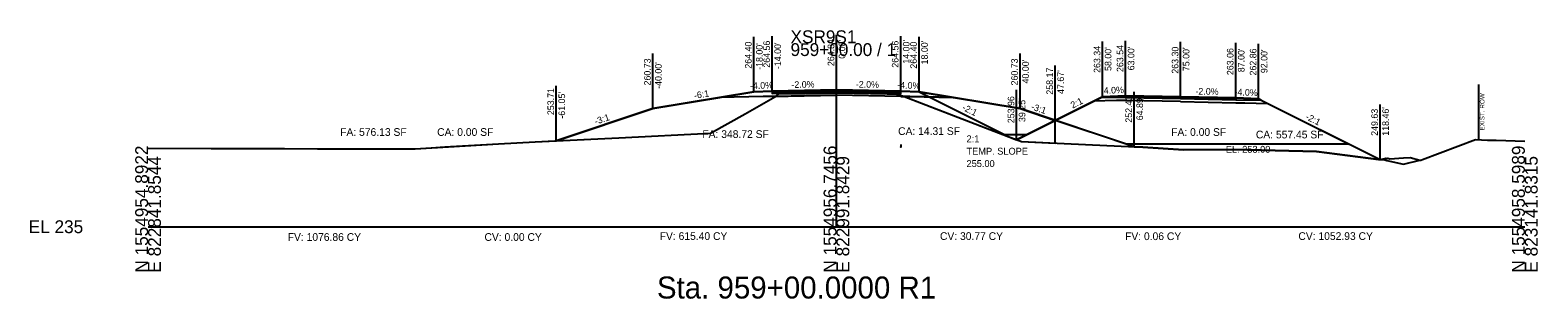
# Model space of a CAD drawing. Extents: x -26 to 823017, y -16 to 1558356.
# Drawn here: x -25.7 to 302.8, y 6984.3 to 7042.8 of the extents above; entities that cross this region are included whole.
import ezdxf

# ---------------------------------------------------------------- set-up
doc = ezdxf.new("R2010")
doc.units = 0
for name, color, linetype in [('ASPHALT_19MM1', 7, 'Continuous'), ('ASPHALT_9_5MM1', 7, 'Continuous'), ('CONST_DCH', 7, 'Continuous'), ('CONST_LV3', 7, 'Continuous'), ('Default', 7, 'Continuous'), ('Draft_XS_Grid', 7, 'Continuous'), ('Draft_XS_Text', 7, 'Continuous'), ('DTM_CORRIDOR', 7, 'Continuous'), ('DTM_P_FINISHED_GRADE2', 7, 'Continuous'), ('DTM_TEMP_DROP', 7, 'Continuous'), ('DTM_X_GROUND', 7, 'Continuous'), ('PROFILES_DCH_2', 7, 'Continuous'), ('SLOPE_STAKES_FILL', 7, 'Continuous'), ('XS_CELL', 7, 'Continuous'), ('XS_M_SHAPES_EARTHWORK', 7, 'Continuous'), ('XS_P_ASPHALT', 7, 'Continuous'), ('XS_P_DR_GRAVEL', 7, 'Continuous'), ('XS_P_GROUND', 7, 'Continuous'), ('XS_P_NULL_POINT', 7, 'Continuous'), ('XS_P_SHOULDER', 7, 'Continuous'), ('XS_P_SUBGRADE_GRANULAR', 7, 'Continuous'), ('XS_P_SUBGRADE_MILLING', 7, 'Continuous'), ('XS_P_SUBGRADE_UNDERCUT', 7, 'Continuous'), ('XS_P_TX_CLEARZONE', 7, 'Continuous'), ('XS_P_TX_FS_BS', 7, 'Continuous'), ('XS_SHEET_EW_TX_AREA', 7, 'Continuous'), ('XS_SHEET_EW_TX_VOLUME', 7, 'Continuous'), ('XS_X_ROW', 7, 'Continuous')]:
    doc.layers.add(name, color=color, linetype=linetype)

msp = doc.modelspace()

# ---------------------------------------------------------------- linework, layer by layer
at = {"layer": 'ASPHALT_19MM1'}
for points in [[(136, 7029.27), (136, 7029.06), (150, 7029.34), (150, 7029.34), (150, 7029.34), (164, 7029.06), (164, 7029.27), (164, 7029.27), (150, 7029.55), (150, 7029.55), (150, 7029.55), (136, 7029.27), (136, 7029.27)], [(213, 7028.16), (225, 7027.92), (237, 7027.68), (237, 7027.89), (225, 7028.13), (213, 7028.37), (213, 7028.16)]]:
    msp.add_lwpolyline(points, dxfattribs=at)
at = {"layer": 'ASPHALT_9_5MM1'}
msp.add_lwpolyline([(136, 7029.56), (136, 7029.43), (150, 7029.71), (150, 7029.71), (150, 7029.71), (164, 7029.43), (164, 7029.56), (164, 7029.56), (150, 7029.84), (150, 7029.84), (150, 7029.84), (136, 7029.56), (136, 7029.56)], dxfattribs=at)
at = {"layer": 'CONST_DCH'}
msp.add_lwpolyline([(213, 7028.37), (225, 7028.13), (237, 7027.89), (237, 7028.06), (225, 7028.3), (213, 7028.54), (213, 7028.37)], dxfattribs=at)
at = {"layer": 'CONST_LV3'}
for points in [[(110, 7025.73), (124.59, 7028.16), (124.59, 7028.16)], [(150, 7029.84), (164, 7029.56)], [(168, 7029.4), (164, 7029.56), (164, 7029.56)], [(190, 7025.73), (175.41, 7028.16), (175.41, 7028.16)], [(189.25, 7018.96), (189.25, 7018.96), (208, 7028.34), (208, 7028.34), (213, 7028.54)], [(197.67, 7023.17), (197.67, 7023.17), (208, 7028.34), (208, 7028.34), (213, 7028.54), (225, 7028.3), (225, 7028.3), (237, 7028.06), (237, 7028.06), (237, 7028.06), (242, 7027.86), (242, 7027.86), (242, 7027.86), (242, 7027.86), (242, 7027.86), (242, 7027.86), (242, 7027.86), (242, 7027.86), (268.46, 7014.63), (269.52, 7014.87), (269.69, 7014.91), (269.7, 7014.91), (269.94, 7014.87), (270.16, 7014.91), (270.59, 7014.79), (273.59, 7015), (275, 7015.11), (277.13, 7014.48), (277.36, 7014.53), (277.7, 7014.68), (289.27, 7019), (291.84, 7018.88), (293.73, 7018.86), (300, 7018.65)], [(242, 7027.86), (268.46, 7014.63)], [(0, 7017.11), (13.73, 7017.07), (29.7, 7017.03), (36.9, 7017.01), (53.92, 7016.98), (58.23, 7017.01), (61.68, 7017.21), (64.64, 7017.39), (65.92, 7017.46), (76.37, 7018.08), (84.38, 7018.48), (88.61, 7018.7), (88.95, 7018.71)], [(164, 7017.9), (164, 7017.36), (164, 7017.38)]]:
    msp.add_lwpolyline(points, dxfattribs=at)
at = {"layer": 'Default'}
msp.add_lwpolyline([(136, 7029.43), (136, 7029.27), (150, 7029.55), (150, 7029.55), (150, 7029.55), (164, 7029.27), (164, 7029.43), (164, 7029.43), (150, 7029.71), (150, 7029.71), (150, 7029.71), (136, 7029.43), (136, 7029.43)], dxfattribs=at)
at = {"layer": 'DTM_P_FINISHED_GRADE2'}
msp.add_lwpolyline([(88.95, 7018.71), (110, 7025.73), (110, 7025.73), (132, 7029.4), (136, 7029.56), (150, 7029.84), (164, 7029.56), (168, 7029.4), (168, 7029.4), (190, 7025.73), (190, 7025.73), (197.67, 7023.17), (197.67, 7023.17)], dxfattribs=at)
at = {"layer": 'DTM_X_GROUND'}
for points in [[(0, 7017.11), (13.73, 7017.07), (29.7, 7017.03), (36.9, 7017.01), (53.92, 7016.98), (58.23, 7017.01), (61.68, 7017.21), (64.64, 7017.39), (65.92, 7017.46), (76.37, 7018.03), (84.38, 7018.47), (88.61, 7018.7), (88.95, 7018.71), (110, 7025.73), (110, 7025.73), (132, 7029.4), (132, 7029.4), (136, 7029.56), (136, 7029.56), (136, 7029.56), (150, 7029.84), (150, 7029.84), (164, 7029.56), (168, 7029.4), (168, 7029.4), (190, 7025.73), (190, 7025.73), (197.67, 7023.17), (197.67, 7023.17), (197.67, 7023.17), (208, 7028.34), (208, 7028.34), (213, 7028.54), (225, 7028.3), (225, 7028.3), (237, 7028.06), (237, 7028.06), (237, 7028.06), (242, 7027.86), (242, 7027.86), (242, 7027.86), (242, 7027.86), (242, 7027.86), (242, 7027.86), (242, 7027.86), (242, 7027.86), (268.46, 7014.63), (269.52, 7014.87), (269.69, 7014.91), (269.7, 7014.91), (269.94, 7014.87), (270.16, 7014.91), (270.59, 7014.79), (273.59, 7015), (275, 7015.11), (277.13, 7014.48), (277.36, 7014.53), (277.7, 7014.68), (289.27, 7019), (291.84, 7018.88), (293.73, 7018.86), (300, 7018.65)], [(0, 7017.11), (13.73, 7017.07), (29.7, 7017.03), (36.9, 7017.01), (53.92, 7016.98), (58.23, 7017.01), (76.37, 7018.08), (84.38, 7018.48), (102.55, 7019.4), (122.59, 7020.4), (130.09, 7024.59), (136.7, 7028.35), (137.06, 7028.67), (137.42, 7028.96), (143.28, 7029.07), (150.17, 7029.21), (161.03, 7028.98), (162.9, 7028.94), (163.17, 7028.86), (164.42, 7028.5), (186.29, 7020.1), (190.33, 7018.55), (208.91, 7017.7), (216.77, 7017.35), (225.63, 7016.77), (236.61, 7016.83), (254.59, 7016.41), (268.12, 7014.64), (269.52, 7014.59), (269.94, 7014.45), (270.59, 7014.32), (273.59, 7013.65), (277.13, 7014.48), (277.36, 7014.53), (277.7, 7014.68), (289.27, 7019), (291.84, 7018.88), (293.73, 7018.86), (300, 7018.65)], [(0, 7017.11), (13.73, 7017.07), (29.7, 7017.03), (36.9, 7017.01), (53.92, 7016.98), (58.23, 7017.01), (76.37, 7018.08), (84.38, 7018.48), (102.55, 7019.4), (122.59, 7020.4), (130.09, 7024.59), (136.7, 7028.35), (137.06, 7028.67), (137.42, 7028.96), (143.28, 7029.07), (150.17, 7029.21), (161.03, 7028.98), (162.9, 7028.94), (163.17, 7028.86), (164.42, 7028.5), (186.29, 7020.1), (189.25, 7018.96), (189.25, 7018.96), (189.25, 7018.96), (208, 7028.34), (208, 7028.34), (213, 7028.54), (225, 7028.3), (225, 7028.3), (237, 7028.06), (237, 7028.06), (237, 7028.06), (242, 7027.86), (242, 7027.86), (242, 7027.86), (242, 7027.86), (242, 7027.86), (242, 7027.86), (242, 7027.86), (242, 7027.86), (268.46, 7014.63), (269.52, 7014.87), (269.69, 7014.91), (269.7, 7014.91), (269.94, 7014.87), (270.16, 7014.91), (270.59, 7014.79), (273.59, 7015), (275, 7015.11), (277.13, 7014.48), (277.36, 7014.53), (277.7, 7014.68), (289.27, 7019), (291.84, 7018.88), (293.73, 7018.86), (300, 7018.65)]]:
    msp.add_lwpolyline(points, dxfattribs=at)
at = {"layer": 'XS_CELL'}
for p, q in [((150, 7000), (150, 7040)), ((0, 7000), (150, 7000)), ((150, 7000), (300, 7000))]:
    msp.add_line(p, q, dxfattribs=at)
at = {"layer": 'XS_M_SHAPES_EARTHWORK'}
for points in [[(88.95, 7018.71), (102.55, 7019.4), (122.59, 7020.4), (130.09, 7024.59), (136.7, 7028.35), (136.76, 7028.41), (136, 7028.39), (134, 7028.35), (124.59, 7028.16), (110, 7025.73)], [(136.76, 7028.41), (137.06, 7028.67), (137.42, 7028.96), (143.28, 7029.07), (150.17, 7029.21), (161.03, 7028.98), (162.9, 7028.94), (163.17, 7028.86), (164.42, 7028.5), (164.74, 7028.38), (164, 7028.39), (150, 7028.67)], [(164.74, 7028.38), (186.29, 7020.1), (190.33, 7018.55), (197.67, 7018.21), (197.67, 7023.17), (190, 7025.73), (175.41, 7028.16), (166, 7028.35)]]:
    msp.add_lwpolyline(points, close=True, dxfattribs=at)
at = {"layer": 'XS_P_DR_GRAVEL'}
for points in [[(208, 7028.34), (208, 7028.34), (207.86, 7028.27), (213, 7028.16), (213, 7028.16), (213, 7028.16), (213, 7028.54), (208, 7028.34)], [(242, 7027.86), (237, 7028.06), (237, 7027.68), (237, 7027.68), (242.57, 7027.57), (242.57, 7027.57), (242.57, 7027.57), (242, 7027.86), (242, 7027.86)]]:
    msp.add_lwpolyline(points, dxfattribs=at)
at = {"layer": 'XS_P_GROUND'}
for p in [(168, 7029.4), (191.32, 7020)]:
    msp.add_line(p, (186.79, 7020), dxfattribs=at)
for points in [[(132, 7029.4), (110, 7025.73), (88.95, 7018.71)], [(197.67, 7023.17), (197.67, 7023.17), (190, 7025.73), (168, 7029.4), (168, 7029.4)], [(214.89, 7017.43), (214.89, 7017.43), (190, 7025.73), (168, 7029.4), (168, 7029.4)], [(208, 7028.34), (189.25, 7018.96)], [(242, 7027.86), (268.46, 7014.63)], [(268.46, 7014.63), (268.12, 7014.64), (268.12, 7014.64), (254.59, 7016.41), (254.59, 7016.41), (254.59, 7016.41), (236.61, 7016.83), (236.61, 7016.83), (225.63, 7016.77), (216.77, 7017.35), (216.77, 7017.35), (214.89, 7017.43), (214.89, 7017.43)], [(214.89, 7017.43), (214.89, 7017.43), (216.77, 7017.35), (216.77, 7017.35), (225.63, 7016.77), (236.61, 7016.83), (236.61, 7016.83), (254.59, 7016.41), (254.59, 7016.41), (254.59, 7016.41), (268.12, 7014.64), (268.12, 7014.64), (268.46, 7014.63)]]:
    msp.add_lwpolyline(points, dxfattribs=at)
at = {"layer": 'XS_P_SHOULDER'}
for points in [[(136, 7029.56), (132, 7029.4)], [(164, 7029.56), (168, 7029.4)], [(208, 7028.34), (208, 7028.34), (213, 7028.54)], [(242, 7027.86), (242, 7027.86), (237, 7028.06)]]:
    msp.add_lwpolyline(points, dxfattribs=at)
at = {"layer": 'XS_P_SUBGRADE_GRANULAR'}
for points in [[(136, 7028.39), (134, 7028.35), (124.59, 7028.16)], [(136, 7028.39), (150, 7028.67), (150, 7028.67)], [(164, 7028.39), (150, 7028.67), (150, 7028.67)], [(164, 7028.39), (166, 7028.35), (175.41, 7028.16)], [(213, 7027.5), (211, 7027.54), (206, 7027.34)], [(225, 7027.26), (213, 7027.5)], [(225, 7027.26), (237, 7027.02)], [(237, 7027.02), (239, 7026.98), (243.96, 7026.88)]]:
    msp.add_lwpolyline(points, dxfattribs=at)
at = {"layer": 'XS_P_SUBGRADE_UNDERCUT'}
msp.add_lwpolyline([(213.19, 7018), (197.67, 7023.17), (208, 7028.34), (213, 7028.54), (225, 7028.3), (237, 7028.06), (242, 7027.86), (261.72, 7018)], close=True, dxfattribs=at)
at = {"layer": 'XS_P_TX_CLEARZONE'}
for p, q in [((132, 7029.4), (132, 7041.4)), ((136, 7029.56), (136, 7041.56)), ((150, 7029.84), (150, 7041.84)), ((164, 7029.56), (164, 7041.56)), ((168, 7029.4), (168, 7041.4)), ((168, 7029.4), (168, 7041.4)), ((213, 7028.54), (213, 7040.54)), ((110, 7025.73), (110, 7037.73)), ((190, 7025.73), (190, 7037.73)), ((190, 7025.73), (190, 7037.73)), ((208, 7028.34), (208, 7040.34)), ((225, 7028.3), (225, 7040.3)), ((237, 7028.06), (237, 7040.06)), ((242, 7027.86), (242, 7039.86)), ((197.67, 7023.17), (197.67, 7035.17)), ((88.95, 7018.71), (88.95, 7030.71)), ((189.25, 7018.96), (189.25, 7029.86)), ((214.89, 7017.43), (214.89, 7029.43)), ((268.46, 7014.63), (268.46, 7026.63))]:
    msp.add_line(p, q, dxfattribs=at)
at = {"layer": 'XS_X_ROW'}
msp.add_line((290, 7018.97), (290, 7030.97), dxfattribs=at)

# ---------------------------------------------------------------- texts
at = {"layer": 'CONST_DCH'}
for p in [(189.17, 7018.84), (268.38, 7014.51), (268.38, 7014.51)]:
    msp.add_text('X', height=0.24, dxfattribs=at).set_placement(p)
at = {"layer": 'Draft_XS_Grid'}
msp.add_text('-', height=0.0001, dxfattribs=at).set_placement((0, 7000))
at = {"layer": 'Draft_XS_Text'}
msp.add_text('Sta. 959+00.0000 R1', height=4.8, dxfattribs=at).set_placement((110.88, 6984.35))
at = {"layer": 'DTM_CORRIDOR'}
for p in [(212.92, 7028.42), (224.92, 7028.18), (236.92, 7027.94)]:
    msp.add_text('X', height=0.24, dxfattribs=at).set_placement(p)
at = {"layer": 'DTM_TEMP_DROP'}
for p in [(135.92, 7029.44), (149.92, 7029.72), (163.92, 7029.44)]:
    msp.add_text('X', height=0.24, dxfattribs=at).set_placement(p)
at = {"layer": 'PROFILES_DCH_2'}
for p in [(167.92, 7029.28), (189.92, 7025.61), (214.81, 7017.31), (268.38, 7014.51)]:
    msp.add_text('X', height=0.24, dxfattribs=at).set_placement(p)
at = {"layer": 'SLOPE_STAKES_FILL'}
for p in [(197.59, 7023.05), (88.87, 7018.59)]:
    msp.add_text('X', height=0.24, dxfattribs=at).set_placement(p)
at = {"layer": 'XS_CELL'}
for s, p in [('XSR9S1', (140, 7040)), ('959+00.00 / 1', (140, 7037.2)), ('EL 235', (-26, 6998.6))]:
    msp.add_text(s, height=2.8, dxfattribs=at).set_placement(p)
for s, p in [('N 1554954.8922', (0, 6990)), ('N 1554956.7456', (150, 6990)), ('N 1554958.5989', (300, 6990)), ('E 822841.8544', (2.8, 6990)), ('E 822991.8429', (152.8, 6990)), ('E 823141.8315', (302.8, 6990))]:
    msp.add_text(s, height=2.8, rotation=90, dxfattribs=at).set_placement(p)
at = {"layer": 'XS_P_ASPHALT'}
for p in [(189.17, 7018.84), (268.38, 7014.51)]:
    msp.add_text('X', height=0.24, dxfattribs=at).set_placement(p)
at = {"layer": 'XS_P_GROUND'}
for s, p in [('2:1', (178.35, 7018.41)), ('TEMP. SLOPE', (178.35, 7015.71)), ('255.00', (178.35, 7013.01))]:
    msp.add_text(s, height=1.5, dxfattribs=at).set_placement(p)
at = {"layer": 'XS_P_NULL_POINT'}
for p in [(197.59, 7023.05), (88.87, 7018.59)]:
    msp.add_text('X', height=0.24, dxfattribs=at).set_placement(p)
at = {"layer": 'XS_P_SHOULDER'}
for p in [(207.92, 7028.22), (241.92, 7027.74), (109.92, 7025.61), (189.92, 7025.61)]:
    msp.add_text('X', height=0.24, dxfattribs=at).set_placement(p)
at = {"layer": 'XS_P_SUBGRADE_MILLING'}
for p in [(131.92, 7029.28), (167.92, 7029.28)]:
    msp.add_text('X', height=0.24, dxfattribs=at).set_placement(p)
at = {"layer": 'XS_P_SUBGRADE_UNDERCUT'}
msp.add_text('EL. 253.00', height=1.5, dxfattribs=at).set_placement((234.85, 7016.12))
at = {"layer": 'XS_P_TX_CLEARZONE'}
for s, p in [('264.56', (135.52, 7034.66)), ('264.84', (149.52, 7035.01)), ("0.00'", (151.92, 7036.62)), ('264.56', (163.52, 7034.66)), ("14.00'", (165.92, 7035.53)), ("18.00'", (169.92, 7035.37)), ('264.40', (131.52, 7034.45)), ("-18.00'", (133.92, 7034.19)), ("-14.00'", (137.92, 7034.35)), ('264.40', (167.52, 7034.45)), ('263.34', (207.52, 7033.52)), ("58.00'", (209.92, 7033.95)), ('263.54', (212.52, 7033.72)), ("63.00'", (214.92, 7034.08)), ('263.30', (224.52, 7033.35)), ("75.00'", (226.92, 7033.91)), ('263.06', (236.52, 7033.04)), ("87.00'", (238.92, 7033.67)), ('262.86', (241.52, 7032.96)), ("92.00'", (243.92, 7033.47)), ('260.73', (109.52, 7030.79)), ("-40.00'", (111.92, 7030.05)), ('260.73', (189.52, 7030.79)), ("40.00'", (191.92, 7031.22)), ('258.17', (197.19, 7028.78)), ("47.67'", (199.59, 7028.94)), ('253.71', (88.47, 7024.32)), ("-61.05'", (90.87, 7023.55)), ('253.96', (188.77, 7022.56)), ("39.25'", (191.17, 7022.82)), ('252.43', (214.41, 7022.68)), ("64.89'", (216.81, 7023.2)), ('249.63', (267.98, 7019.81)), ("118.46'", (270.38, 7019.83))]:
    msp.add_text(s, height=1.44, rotation=90, dxfattribs=at).set_placement(p)
at = {"layer": 'XS_P_TX_FS_BS'}
for s, rotation, p in [('-4.0%', 2.2906, (131.18, 7029.97)), ('-2.0%', 1.1458, (140.2, 7030.24)), ('-2.0%', 358.8542, (154.22, 7030.35)), ('-4.0%', 357.7094, (163.23, 7030.19)), ('-6:1', 9.4642, (119.08, 7027.85)), ('2:1', 26.5651, (201.47, 7025.74)), ('4.0%', 2.2906, (208.27, 7028.95)), ('-2.0%', 358.8542, (228.22, 7028.83)), ('-4.0%', 357.7094, (236.73, 7028.67)), ('-3:1', 18.4332, (97.56, 7022.22)), ('-2:1', 333.8479, (177.26, 7025.52)), ('-3:1', 341.5624, (192.3, 7025.59)), ('-2:1', 333.4349, (252.08, 7023.49))]:
    msp.add_text(s, height=1.44, rotation=rotation, dxfattribs=at).set_placement(p)
at = {"layer": 'XS_SHEET_EW_TX_AREA'}
for s, p in [('FA: 576.13 SF', (41.86, 7019.8)), ('CA: 0.00 SF', (63, 7019.8)), ('FA: 348.72 SF', (120.78, 7019.35)), ('CA: 14.31 SF', (163.44, 7020)), ('FA: 0.00 SF', (222.94, 7019.8)), ('CA: 557.45 SF', (241.4, 7019.25))]:
    msp.add_text(s, height=1.68, dxfattribs=at).set_placement(p)
at = {"layer": 'XS_SHEET_EW_TX_VOLUME'}
for s, p in [('FV: 1076.86 CY', (30.43, 6996.92)), ('CV: 0.00 CY', (73.31, 6996.92)), ('FV: 615.40 CY', (111.49, 6997.12)), ('CV: 30.77 CY', (172.56, 6997.12)), ('FV: 0.06 CY', (212.89, 6997.09)), ('CV: 1052.93 CY', (250.66, 6997.12))]:
    msp.add_text(s, height=1.68, dxfattribs=at).set_placement(p)
at = {"layer": 'XS_X_ROW'}
msp.add_text('EXIST. ROW', height=1, rotation=90, dxfattribs=at).set_placement((291.2, 7020.97))

doc.saveas('drawing.dxf')
